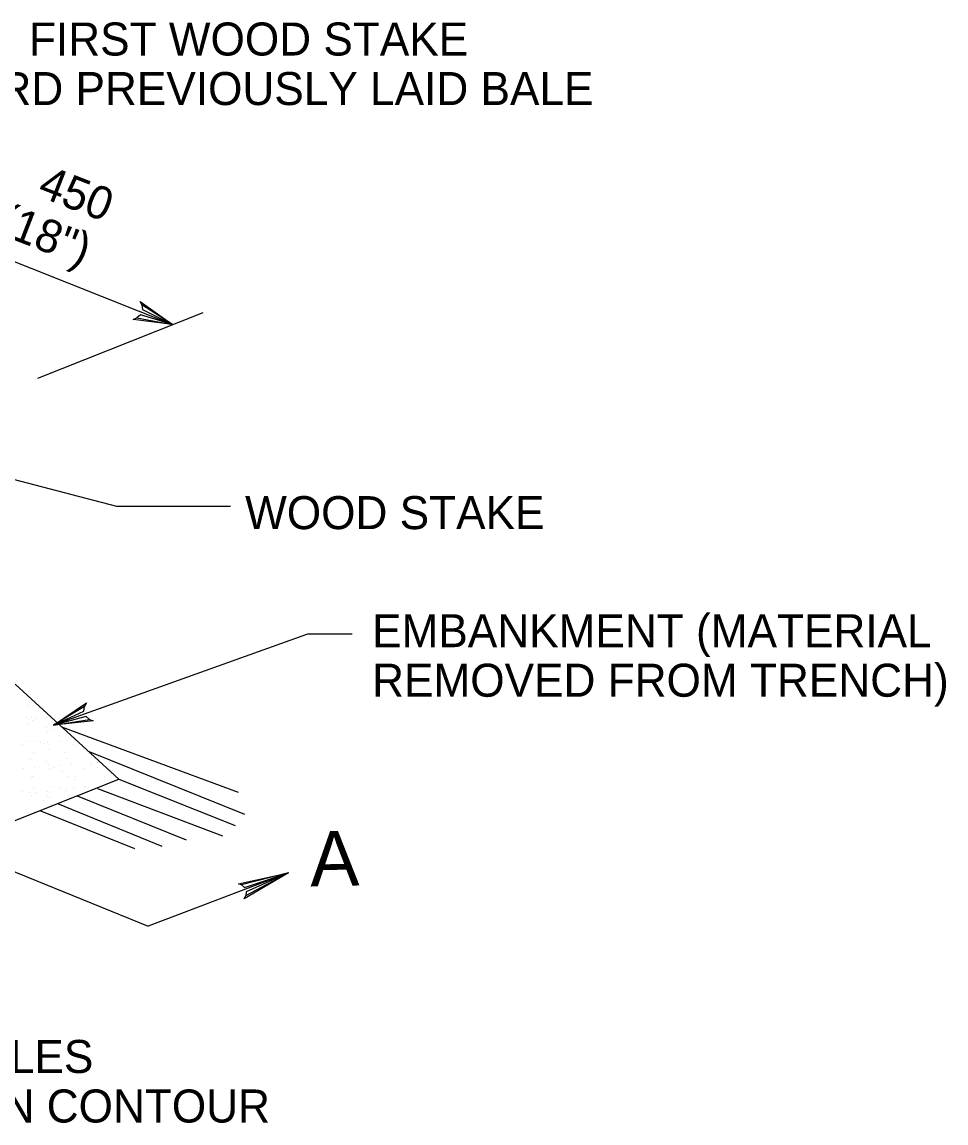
# Model space of a CAD drawing. Extents: x 636462 to 637367, y 299944 to 300538.
# Drawn here: x 636723 to 636806.9, y 300049.1 to 300149.1 of the extents above; entities that cross this region are included whole.
import ezdxf

# ---------------------------------------------------------------- set-up
doc = ezdxf.new("R2010")
doc.units = 0
doc.layers.add('Default', color=7, linetype='Continuous')

msp = doc.modelspace()

# ---------------------------------------------------------------- linework, layer by layer
at = {"layer": 'Default'}
for p, q in [((636707.118, 300133.374), (636736.655, 300121.596)), ((636724.428, 300116.747), (636739.436, 300122.699)), ((636625.772, 300111.279), (636734.467, 300066.973)), ((636722.375, 300088.958), (636731.791, 300080.316)), ((636723.05, 300087.911), (636723.05, 300087.911)), ((636723.507, 300087.047), (636723.507, 300087.047)), ((636725.268, 300086.283), (636725.268, 300086.283)), ((636723.417, 300085.905), (636723.417, 300085.905)), ((636723.551, 300085.738), (636723.551, 300085.738)), ((636723.586, 300085.397), (636723.586, 300085.397)), ((636723.886, 300085.9), (636723.886, 300085.9)), ((636723.943, 300085.675), (636723.943, 300085.675)), ((636724.2, 300085.797), (636724.2, 300085.797)), ((636725.214, 300085.888), (636725.214, 300085.888)), ((636725.127, 300085.119), (636725.127, 300085.119)), ((636725.346, 300084.633), (636725.346, 300084.633)), ((636725.357, 300084.974), (636725.357, 300084.974)), ((636725.836, 300084.847), (636725.836, 300084.847)), ((636726.442, 300084.291), (636726.442, 300084.291)), ((636726.594, 300085.086), (636742.639, 300079.131)), ((636723.007, 300083.471), (636723.007, 300083.471)), ((636723.664, 300083.746), (636723.664, 300083.746)), ((636724.424, 300083.76), (636724.424, 300083.76)), ((636724.701, 300083.624), (636724.701, 300083.624)), ((636724.95, 300083.53), (636724.95, 300083.53)), ((636725.35, 300083.683), (636725.35, 300083.683)), ((636726.364, 300083.775), (636726.364, 300083.775)), ((636727.033, 300083.83), (636727.033, 300083.83)), ((636727.683, 300083.51), (636727.683, 300083.51)), ((636727.913, 300083.365), (636727.913, 300083.365)), ((636723.934, 300082.758), (636723.934, 300082.758)), ((636724.164, 300082.614), (636724.164, 300082.614)), ((636725.425, 300082.982), (636725.425, 300082.982)), ((636726.843, 300082.702), (636726.843, 300082.702)), ((636728.615, 300082.972), (636728.615, 300082.972)), ((636728.998, 300082.683), (636728.998, 300082.683)), ((636729.005, 300082.873), (636743.197, 300077.134)), ((636723.143, 300081.266), (636723.143, 300081.266)), ((636723.743, 300082.096), (636723.743, 300082.096)), ((636724.157, 300081.357), (636724.157, 300081.357)), ((636725.249, 300081.931), (636725.249, 300081.931)), ((636725.431, 300081.615), (636725.431, 300081.615)), ((636725.503, 300081.332), (636725.503, 300081.332)), ((636725.85, 300081.51), (636725.85, 300081.51)), ((636725.957, 300081.385), (636725.957, 300081.385)), ((636726.5, 300081.569), (636726.5, 300081.569)), ((636727.111, 300082.179), (636727.111, 300082.179)), ((636727.513, 300081.661), (636727.513, 300081.661)), ((636728.694, 300081.321), (636728.694, 300081.321)), ((636729.207, 300081.814), (636729.207, 300081.814)), ((636729.315, 300081.62), (636729.315, 300081.62)), ((636729.841, 300081.39), (636729.841, 300081.39)), ((636729.856, 300081.873), (636729.856, 300081.873)), ((636653.687, 300049.343), (636731.791, 300080.316)), ((636723.821, 300080.445), (636723.821, 300080.445)), ((636723.967, 300080.552), (636723.967, 300080.552)), ((636726.491, 300081.149), (636726.491, 300081.149)), ((636726.72, 300081.005), (636726.72, 300081.005)), ((636727.19, 300080.529), (636727.19, 300080.529)), ((636727.805, 300080.322), (636727.805, 300080.322)), ((636727.85, 300080.557), (636727.85, 300080.557)), ((636730.454, 300080.557), (636730.454, 300080.557)), ((636731.788, 300080.315), (636742.359, 300076.117)), ((636723.081, 300079.235), (636723.081, 300079.235)), ((636724.056, 300079.57), (636724.056, 300079.57)), ((636725.306, 300079.243), (636725.306, 300079.243)), ((636725.582, 300079.681), (636725.582, 300079.681)), ((636726.438, 300079.47), (636726.438, 300079.47)), ((636726.964, 300079.24), (636726.964, 300079.24)), ((636727, 300079.397), (636727, 300079.397)), ((636727.649, 300079.455), (636727.649, 300079.455)), ((636728.663, 300079.547), (636728.663, 300079.547)), ((636728.772, 300079.671), (636728.772, 300079.671)), ((636729.047, 300079.541), (636729.047, 300079.541)), ((636729.276, 300079.396), (636729.276, 300079.396)), ((636729.863, 300079.49), (636741.216, 300075.166)), ((636723.643, 300079.093), (636723.643, 300079.093)), ((636723.9, 300078.795), (636723.9, 300078.795)), ((636724.293, 300079.152), (636724.293, 300079.152)), ((636724.974, 300078.407), (636724.974, 300078.407)), ((636725.298, 300078.789), (636725.298, 300078.789)), ((636725.528, 300078.644), (636725.528, 300078.644)), ((636727.268, 300078.878), (636727.268, 300078.878)), ((636728.008, 300078.816), (636737.9, 300074.816)), ((636723.562, 300077.321), (636723.562, 300077.321)), ((636724.616, 300077.471), (636733.206, 300074.016)), ((636725.661, 300078.031), (636725.661, 300078.031)), ((636726.227, 300078.11), (636735.711, 300074.251)), ((636747.186, 300071.809), (636734.467, 300066.973))]:
    msp.add_line(p, q, dxfattribs=at)
for points in [[(636733.894, 300123.392), (636733.727, 300123.699), (636736.655, 300121.596), (636733.894, 300123.392), (636733.937, 300122.973), (636736.655, 300121.596), (636733.747, 300122.484), (636733.438, 300122.204), (636736.655, 300121.596), (636733.082, 300122.074), (636733.438, 300122.204)], [(636741.914, 300105.074), (636731.615, 300105.074), (636690.459, 300115.838)], [(636752.962, 300093.5), (636748.933, 300093.5), (636725.873, 300085.218)], [(636729.127, 300085.735), (636729.456, 300085.618), (636725.873, 300085.218), (636729.127, 300085.735), (636728.813, 300086.017), (636725.873, 300085.218), (636728.627, 300086.506), (636728.669, 300086.921), (636725.873, 300085.218), (636728.847, 300087.257), (636728.669, 300086.921)], [(636742.926, 300070.734), (636743.192, 300070.499), (636747.186, 300071.809), (636742.926, 300070.734), (636742.648, 300070.831), (636747.186, 300071.809), (636743.355, 300070.091), (636743.326, 300069.745), (636747.186, 300071.809), (636743.182, 300069.465), (636743.326, 300069.745)]]:
    msp.add_lwpolyline(points, dxfattribs=at)

# ---------------------------------------------------------------- texts
for s, height, p in [('ANGLE FIRST WOOD STAKE', 2.99804, (636708.931, 300146.029)), ('TOWARD PREVIOUSLY LAID BALE', 2.99804, (636708.931, 300141.532)), ('WOOD STAKE', 2.998, (636743.255, 300103.025)), ('EMBANKMENT (MATERIAL ', 2.99804, (636754.782, 300092.305)), ('REMOVED FROM TRENCH)', 2.99804, (636754.782, 300087.808)), ('BOUND BALES', 2.99804, (636700.963, 300053.645)), ('PLACED ON CONTOUR', 2.99804, (636700.963, 300049.147))]:
    msp.add_text(s, height=height, dxfattribs=at).set_placement(p)
for s, height, rotation, p in [('450', 2.998, 338.77426, (636724.292, 300133.317)), ('(18")', 2.998, 338.77426, (636720.563, 300129.941)), ('A', 4.997, 1.26463, (636749.191, 300070.575))]:
    msp.add_text(s, height=height, rotation=rotation, dxfattribs=at).set_placement(p)

doc.saveas('drawing.dxf')
